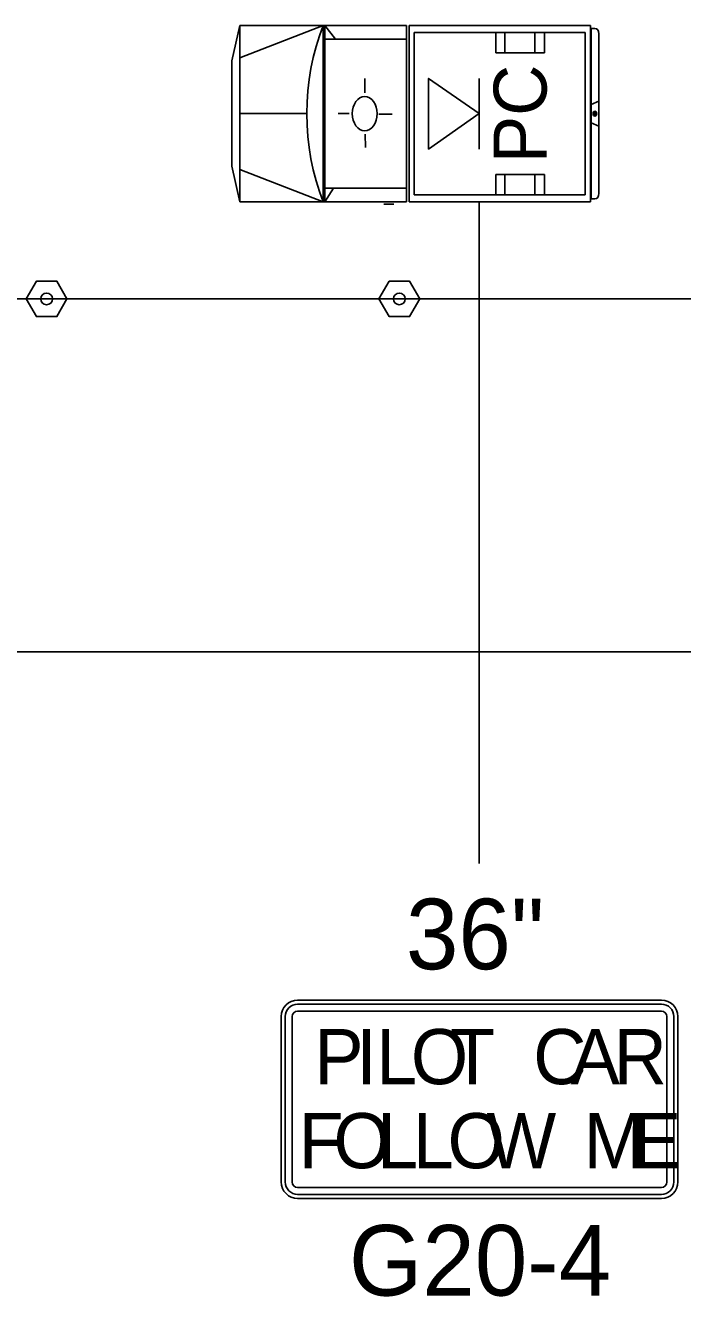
# Model space of a CAD drawing. Extents: x 99998.9 to 100095.7, y 99995 to 100010.7.
# Drawn here: x 100046.326 to 100047.071, y 100005.001 to 100006.442 of the extents above; entities that cross this region are included whole.
import ezdxf

# ---------------------------------------------------------------- set-up
doc = ezdxf.new("R2010")
doc.units = 0
for name, color, linetype in [('RD_ED_ShoulderPavedEdge', 7, 'Continuous'), ('RD_MK_LineEdgeWhite', 7, 'Continuous'), ('TR_SN_ConstructionSigns', 7, 'Continuous'), ('TR_WZ_MotoristVehicle', 7, 'Continuous'), ('TR_WZ_PortableSignMountBlk-Wht', 7, 'Continuous'), ('TR_WZ_TubularMarker', 7, 'Continuous'), ('TR_WZ_WorkZoneDetails', 7, 'Continuous')]:
    doc.layers.add(name, color=color, linetype=linetype)

msp = doc.modelspace()

# ---------------------------------------------------------------- linework, layer by layer
at = {"layer": 'RD_ED_ShoulderPavedEdge'}
msp.add_line((100040.1076, 100005.7323), (100055.6424, 100005.7323), dxfattribs=at)
at = {"layer": 'RD_MK_LineEdgeWhite'}
msp.add_line((100040.1076, 100006.1323), (100055.6424, 100006.1323), dxfattribs=at)
at = {"layer": 'TR_SN_ConstructionSigns'}
for p, q in [((100047.0472, 100005.3373), (100046.6347, 100005.3373)), ((100047.0472, 100005.3326), (100046.6347, 100005.3326)), ((100047.0472, 100005.3326), (100047.0472, 100005.3326)), ((100046.6159, 100005.3186), (100046.6159, 100005.1311)), ((100046.6206, 100005.3186), (100046.6206, 100005.3186)), ((100046.6206, 100005.3186), (100046.6206, 100005.1311)), ((100046.6284, 100005.1311), (100046.6284, 100005.3186)), ((100046.6347, 100005.3248), (100047.0472, 100005.3248)), ((100047.0534, 100005.3186), (100047.0534, 100005.1311)), ((100047.0612, 100005.1311), (100047.0612, 100005.3186)), ((100047.0659, 100005.1311), (100047.0659, 100005.3186)), ((100047.0472, 100005.1248), (100046.6347, 100005.1248)), ((100047.0612, 100005.1311), (100047.0612, 100005.1311)), ((100046.6347, 100005.117), (100046.6347, 100005.117)), ((100046.6347, 100005.117), (100047.0472, 100005.117)), ((100046.6347, 100005.1123), (100047.0472, 100005.1123))]:
    msp.add_line(p, q, dxfattribs=at)
for centre, radius, start, end in [((100046.6347, 100005.3186), 0.0187, 90, 180), ((100046.6347, 100005.3186), 0.0141, 90, 180), ((100047.0472, 100005.3186), 0.0187, 0, 90), ((100047.0472, 100005.3186), 0.0141, 0, 90), ((100046.6347, 100005.3186), 0.00625, 90, 180), ((100047.0472, 100005.3186), 0.00625, 0, 90), ((100046.6347, 100005.1311), 0.0187, 180, 270), ((100046.6347, 100005.1311), 0.0141, 180, 270), ((100046.6347, 100005.1311), 0.00625, 180, 270), ((100047.0472, 100005.1311), 0.0141, 270, 0), ((100047.0472, 100005.1311), 0.00625, 270, 0), ((100047.0472, 100005.1311), 0.0187, 270, 0)]:
    msp.add_arc(centre, radius, start, end, dxfattribs=at)
at = {"layer": 'TR_WZ_MotoristVehicle'}
for p, q in [((100046.5693, 100006.4423), (100046.56, 100006.402)), ((100046.5693, 100006.4423), (100046.5693, 100006.2423)), ((100046.5693, 100006.4423), (100046.7582, 100006.4423)), ((100046.5693, 100006.4057), (100046.6638, 100006.4423)), ((100046.6638, 100006.4423), (100046.6638, 100006.2423)), ((100046.6655, 100006.4423), (100046.6655, 100006.2423)), ((100046.6655, 100006.4423), (100046.6775, 100006.4268)), ((100046.7582, 100006.4423), (100046.7582, 100006.2423)), ((100046.9667, 100006.4423), (100046.761, 100006.4423)), ((100046.761, 100006.4423), (100046.761, 100006.2423)), ((100046.9667, 100006.4423), (100046.9667, 100006.2423)), ((100046.9718, 100006.439), (100046.9674, 100006.439)), ((100046.9674, 100006.439), (100046.9674, 100006.2456)), ((100046.6655, 100006.4268), (100046.7582, 100006.4268)), ((100046.9608, 100006.4344), (100046.7668, 100006.4344)), ((100046.7668, 100006.4344), (100046.7668, 100006.2503)), ((100046.8595, 100006.4344), (100046.8595, 100006.4113)), ((100046.8695, 100006.4344), (100046.8695, 100006.4113)), ((100046.9035, 100006.4344), (100046.9035, 100006.4113)), ((100046.9145, 100006.4344), (100046.9145, 100006.4113)), ((100046.9608, 100006.4344), (100046.9608, 100006.2503)), ((100046.9763, 100006.4329), (100046.9763, 100006.2517)), ((100046.9145, 100006.4113), (100046.8595, 100006.4113)), ((100046.56, 100006.402), (100046.56, 100006.2827)), ((100046.7108, 100006.382), (100046.7108, 100006.3658)), ((100046.9763, 100006.3564), (100046.9674, 100006.3527)), ((100046.5693, 100006.3423), (100046.6452, 100006.3423)), ((100046.6807, 100006.3425), (100046.6933, 100006.3424)), ((100046.7249, 100006.342), (100046.7249, 100006.342)), ((100046.7417, 100006.3416), (100046.7268, 100006.3419)), ((100046.9739, 100006.3423), (100046.9698, 100006.3423)), ((100046.9718, 100006.3451), (100046.9718, 100006.3395)), ((100046.9763, 100006.3282), (100046.9674, 100006.332)), ((100046.7115, 100006.3039), (100046.7112, 100006.3189)), ((100046.5693, 100006.2423), (100046.56, 100006.2827)), ((100046.5693, 100006.279), (100046.6638, 100006.2423)), ((100046.8595, 100006.2503), (100046.8595, 100006.2733)), ((100046.9145, 100006.2733), (100046.8595, 100006.2733)), ((100046.8695, 100006.2503), (100046.8695, 100006.2733)), ((100046.9035, 100006.2503), (100046.9035, 100006.2733)), ((100046.9145, 100006.2503), (100046.9145, 100006.2733)), ((100046.6655, 100006.2578), (100046.7582, 100006.2578)), ((100046.6754, 100006.2578), (100046.6655, 100006.2423)), ((100046.9608, 100006.2503), (100046.7668, 100006.2503)), ((100046.5693, 100006.2423), (100046.7582, 100006.2423)), ((100046.7324, 100006.2395), (100046.7438, 100006.2395)), ((100046.9667, 100006.2423), (100046.761, 100006.2423)), ((100046.9718, 100006.2456), (100046.9674, 100006.2456))]:
    msp.add_line(p, q, dxfattribs=at)
for centre, major_axis, start_param, end_param in [((100046.7987, 100006.3423), (0, -0.2099), 4.215667, 5.208926), ((100046.9718, 100006.4329), (0, 0.0061), 4.712389, 6.283185), ((100046.9718, 100006.2517), (0, -0.0061), 0, 1.570796)]:
    msp.add_ellipse(centre, major_axis=major_axis, ratio=0.73155, start_param=start_param, end_param=end_param, dxfattribs=at)
for centre, major_axis in [((100046.7108, 100006.3423), (0, 0.0193)), ((100046.9718, 100006.3423), (0, 0.00282))]:
    msp.add_ellipse(centre, major_axis=major_axis, ratio=0.73155, dxfattribs=at)
at = {"layer": 'TR_WZ_PortableSignMountBlk-Wht'}
msp.add_line((100046.8406, 100006.3822), (100046.8406, 100006.3022), dxfattribs=at)
msp.add_lwpolyline([(100046.8406, 100006.3423), (100046.7832, 100006.3022), (100046.7832, 100006.3822)], close=True, dxfattribs=at)
at = {"layer": 'TR_WZ_TubularMarker'}
for points in [[(100046.3269, 100006.1323), (100046.3385, 100006.1523), (100046.3616, 100006.1523), (100046.3731, 100006.1323), (100046.3616, 100006.1123), (100046.3385, 100006.1123)], [(100046.7269, 100006.1323), (100046.7385, 100006.1523), (100046.7616, 100006.1523), (100046.7731, 100006.1323), (100046.7616, 100006.1123), (100046.7385, 100006.1123)]]:
    msp.add_lwpolyline(points, close=True, dxfattribs=at)
for points in [[(100046.3385, 100006.1123), (100046.3616, 100006.1123), (100046.3731, 100006.1323), (100046.3616, 100006.1523), (100046.3385, 100006.1523), (100046.3269, 100006.1323), (100046.3385, 100006.1123)], [(100046.7385, 100006.1123), (100046.7616, 100006.1123), (100046.7731, 100006.1323), (100046.7616, 100006.1523), (100046.7385, 100006.1523), (100046.7269, 100006.1323), (100046.7385, 100006.1123)]]:
    msp.add_lwpolyline(points, dxfattribs=at)
for centre in [(100046.35, 100006.1323), (100046.75, 100006.1323)]:
    msp.add_circle(centre, 0.00667, dxfattribs=at)
at = {"layer": 'TR_WZ_WorkZoneDetails'}
msp.add_line((100046.8406, 100006.2423), (100046.8406, 100005.4923), dxfattribs=at)

# ---------------------------------------------------------------- texts
at = {"layer": 'TR_SN_ConstructionSigns'}
for s, p in [('36"', (100046.7575, 100005.3723)), ('G20-4', (100046.6929, 100005.0023))]:
    msp.add_text(s, height=0.08, rotation=360, dxfattribs=at).set_placement(p)
for s, p in [('P', (100046.6537, 100005.242)), ('I', (100046.7012, 100005.242)), ('L', (100046.7237, 100005.242)), ('O', (100046.7631, 100005.242)), ('T', (100046.8075, 100005.242)), ('C', (100046.9018, 100005.242)), ('A', (100046.9443, 100005.242)), ('R', (100046.9931, 100005.242)), ('F', (100046.6359, 100005.1467)), ('O', (100046.6753, 100005.1467)), ('L', (100046.7247, 100005.1467)), ('L', (100046.7653, 100005.1467)), ('O', (100046.8047, 100005.1467)), ('W', (100046.849, 100005.1467)), ('M', (100046.959, 100005.1467)), ('E', (100047.014, 100005.1467))]:
    msp.add_text(s, height=0.0625, dxfattribs=at).set_placement(p)
at = {"layer": 'TR_WZ_MotoristVehicle'}
msp.add_text('PC', height=0.06, rotation=90, dxfattribs=at).set_placement((100046.917, 100006.2863))

doc.saveas('drawing.dxf')
